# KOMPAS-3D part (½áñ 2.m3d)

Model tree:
1. Эскиз:1
2. Операция выдавливания:1
     Расстояние 1 = 20
3. Эскиз:2
4. Операция выдавливания:2
     Расстояние 1 = 400
5. Эскиз:3
6. Вырезать элемент выдавливания:1
     Расстояние 1 = 70
7. Эскиз:4
8. Вырезать элемент выдавливания:2
     Расстояние 1 = 2
9. Эскиз:5
10. Эскиз:11
11. Вырезать элемент выдавливания:7
     Расстояние 1 = 30
12. Операция выдавливания:3
     Расстояние 1 = 16.96
13. Эскиз:13
14. Вырезать элемент выдавливания:9
     Расстояние 1 = 70
15. Эскиз:14
16. Вырезать элемент выдавливания:10
     Расстояние 1 = 80
